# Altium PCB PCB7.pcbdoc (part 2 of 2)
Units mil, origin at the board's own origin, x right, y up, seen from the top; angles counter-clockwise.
Board outline 4082.91 x 5474.41 mil, 4 copper layers (Top Layer, Inner1, Inner2, Bottom Layer); 133 components, 162 nets, 570 pads, 328 vias.
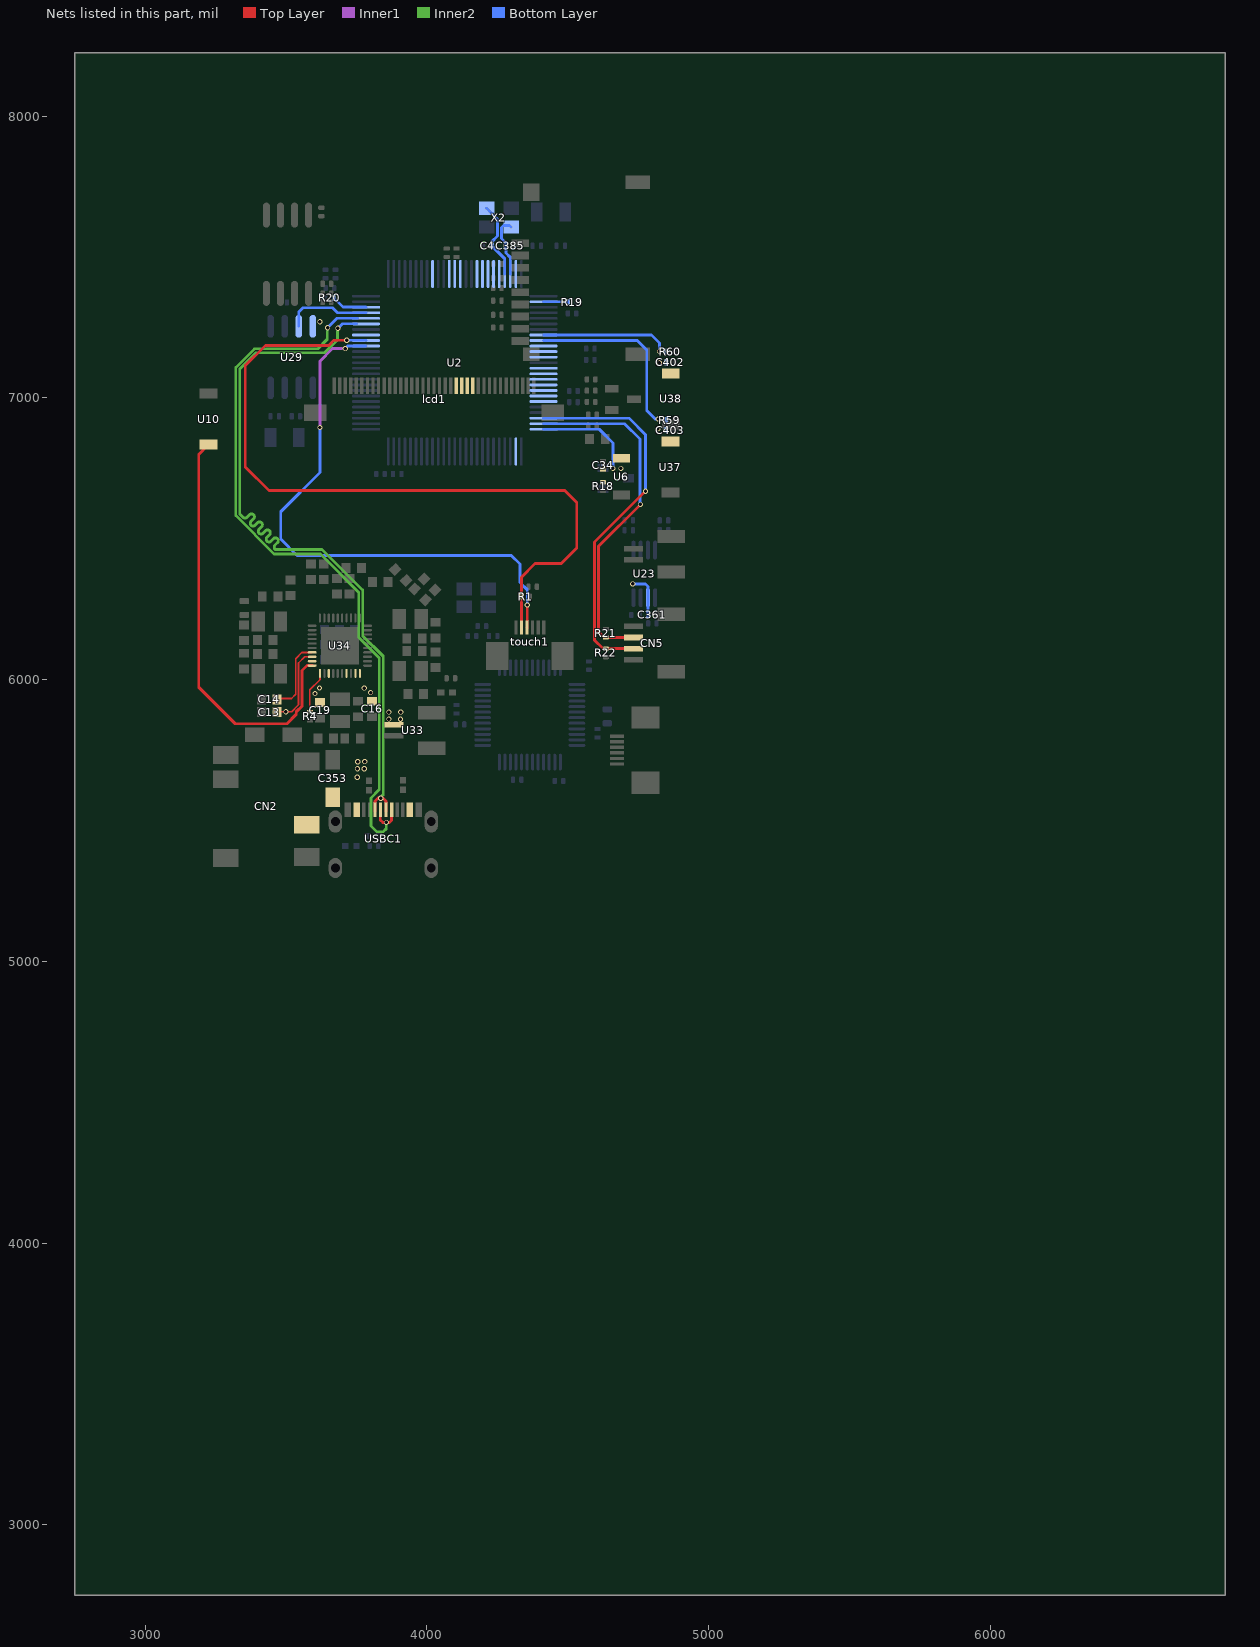
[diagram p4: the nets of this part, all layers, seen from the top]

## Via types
v1: diameter 18.5, hole 12, Top Layer to Bottom Layer, 319 vias
v2: diameter 19.7, hole 7.9, Top Layer to Bottom Layer, 9 vias

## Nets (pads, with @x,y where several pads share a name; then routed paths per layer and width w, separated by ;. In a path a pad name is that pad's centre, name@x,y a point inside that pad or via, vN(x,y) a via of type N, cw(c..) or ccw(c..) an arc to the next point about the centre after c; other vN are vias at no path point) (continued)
PB15: touch1.3 U2.41 | length 1995.7
  Top Layer w10: touch1.3@4355.16,6185.1 4355.72,6185.66 v1(4355.72,6264.41)
  Inner1 w10: v1(3620,6894.41) 3620,7129.41 3665,7174.41 v1(3710,7174.41)
  Bottom Layer w10: v1(3620,6894.41) 3620,6734.21 3481,6595.21 3481,6498.61 3539.2,6440.41 4299,6440.41 4330,6409.41 4330,6344.41 4355.72,6318.69 v1(4355.72,6264.41) ; v1(3710,7174.41) 3719.02,7183.43 U2.41@3783.82,7183.43
PC8: U2.59
PC11: U2.62
PC12: U2.63
PC13: U2.64
PD0: U2.89
PD1: U2.90
PD2: U2.91
PD3: U2.92
PD4: U2.93
PD5: U2.94
PD6: U2.95
PD9: U2.67
PD10: U2.68
PD11: U2.69
PD12: U2.70
PE0: C4.1 U2.72 X2.3 | length 276.9
  Bottom Layer w10: X2.3@4211.69,7672.87 4230,7654.56 4230,7654.37 4250.25,7634.12 4250.25,7573.8 4230,7553.55 C4.1@4230,7539.41 4275.94,7493.46 U2.72@4275.94,7439.33
PE1: C385.1 U2.73 X2.1 | length 217.4
  Bottom Layer w10: U2.73@4295.63,7439.33 4295.63,7498.78 4280,7514.41 C385.1@4280,7539.41 4280,7549.41 4264.25,7565.16 4264.25,7604.41 4271.32,7611.48 4292.77,7611.48 X2.1@4298.31,7605.94
PE2: C402.2 R60.1 U2.83 U38.2 | length 453
  Bottom Layer w10: U2.83@4413.74,7222.8 4796.61,7222.8 4825,7194.41 v1(4825,7164.41)
  other v1: 4825,7124.41
PE3: C403.2 R59.1 U2.84 U37.2 | length 647.6
  Bottom Layer w10: U2.84@4413.74,7203.11 4746.3,7203.11 4780,7169.41 4780,6954.41 4810,6924.41 v1(4820,6924.41)
  other v1: 4820,6889.41
PE4: U2.85
PE5: U2.86
PE6: U2.87
PE8: R1.1 touch1.2 U2.42 | length 2634.5
  Top Layer w10: v1(3715,7204.41) 3670,7204.41 3651.6,7186.01 3426.6,7186.01 3355,7114.41 3355,6754.41 3439,6670.41 4489.2,6670.41 4531.82,6627.79 4531.82,6467.36 4476.4,6411.94 4383.9,6411.94 4335,6363.05 R1.1@4335,6294.41 4335.47,6293.94 touch1.2@4335.47,6185.1
  Bottom Layer w10: v1(3715,7204.41) 3782.52,7204.41 U2.42@3783.82,7203.11
PE9: U2.43
PE11: U2.45 USBC1.A7 USBC1.B7 | length 2645.9
  Top Layer w10: USBC1.B7@3815.47,5532.69 3815.47,5567.95 3826.49,5578.97 v1(3835.61,5578.97) 3843.98,5578.97 3855,5567.95 3855,5532.85 USBC1.A7@3854.84,5532.69
  Inner2 w10: v1@3684.09,7246 3681.98,7243.89 3681.98,7205.37 3636.28,7159.67 3393.32,7159.67 3335.59,7101.94 3335.59,6587.76 3347.48,6575.87 ccw(c3354.56,6582.94) 3361.63,6575.87 3370.43,6584.68 cw(c3377.5,6577.61) 3384.57,6570.54 3375.77,6561.73 ccw(c3382.84,6554.66) 3389.91,6547.59 3398.72,6556.39 cw(c3405.79,6549.32) 3412.86,6542.25 3404.05,6533.45 ccw(c3411.12,6526.37) 3418.2,6519.3 3427,6528.11 cw(c3434.07,6521.04) 3441.14,6513.97 3432.34,6505.16 ccw(c3439.41,6498.09) 3446.48,6491.02 3455.29,6499.83 cw(c3462.36,6492.75) 3469.43,6485.68 3460.62,6476.88 ccw(c3467.69,6469.81) 3460.62,6462.74 3461.75,6461.61 3627.72,6461.61 3771.79,6317.55 3771.79,6155.38 3844.75,6082.42 3844.75,5590.89 v1@3835.93,5582.07
  Bottom Layer w10: v1(3683.88,7246.59) 3699.95,7262.66 U2.45@3750.56,7262.66
PE12: U2.46 USBC1.A6 USBC1.B6 | length 2645.9
  Top Layer w10: USBC1.A6@3834.35,5522.71 3834.35,5501.33 3843.37,5492.3 3867.53,5492.3 3874.66,5499.43 3874.66,5518.83 USBC1.B6@3874.97,5519.15
  Inner2 w10: 3621.57,6445.47 3757.79,6309.26 3757.67,6149.69 3830.75,6076.59 3830.75,5609.16 3801.47,5579.88 3801.47,5480.45 3822.49,5459.42 3844.42,5459.42 3855.41,5470.42 3855.41,5487.44 v1@3854.57,5488.29 ; 3621.57,6446.01 3457.55,6446.01 3321.59,6581.97 3321.59,7107.74 3387.52,7173.67 3612.34,7173.67 3646.32,7207.64 v1@3646.32,7248.37
  Bottom Layer w10: v1(3647.45,7248.41) 3681.27,7282.23 U2.46@3752.89,7282.23
  other v1: 3856.12,5492.93
PE13: U2.47 U29.7 | length 303.3
  Bottom Layer w10: U29.7@3545,7253.56 3545,7304.41 3560,7319.41 3665,7319.41 3682.87,7301.54 U2.47@3783.82,7301.54
PF1: U2.2
PF5: U2.71
PWROK: U34.29
PWRON: U10.2 U34.30 | length 1497.1
  Top Layer w10: U10.2@3225,6833.86 3190,6798.86 3190,5972.78 3319.7,5843.08 3502.72,5843.08 3536.21,5876.57 3536.21,5885.5 3556.03,5905.32 3556.03,6031.51 3574.57,6050.04 3591.75,6050.04 U34.30@3592.56,6049.23
RIGHT: C353.2 CN2.4
RST: C34.2 R18.1 U2.100 U6.1 | length 356.4
  Bottom Layer w10: U2.100@4413.74,6888.15 4611.26,6888.15 4660,6839.41 v1(4660,6749.41)
  other v1: 4688.19,6749.41
RTC: U2.74
SCK: U34.40
SDA: U34.39
SWCLK: CN5.2 R22.1 U2.98 | length 1335.9
  Top Layer w10: CN5.2@4728.07,6109.72 4624.69,6109.72 4595,6139.41 4595,6487.78 v1(4775.77,6668.55)
  Bottom Layer w10: U2.98@4413.74,6927.52 4716.89,6927.52 4775.77,6868.64 v1(4775.77,6668.55)
SWDIO: CN5.3 R21.1 U2.99 | length 1237.7
  Top Layer w10: CN5.3@4728.07,6149.09 4630.32,6149.09 4609,6170.41 4609,6473.14 v1(4757.38,6621.53)
  Bottom Layer w10: U2.99@4413.74,6907.83 4701.57,6907.83 4755.52,6853.89 4755.52,6623.39 v1(4757.38,6621.53)
TS: R4.1 U34.31 | length 152.4
  Top Layer w6: R4.1@3585,5884.41 3584.25,5885.16 3584.25,5963.66 3620.09,5999.5 U34.31@3620.09,6021.7
VBACKUP: C14.1 U34.27 | length 264.3
  Top Layer w6: C14.1@3467.56,5929.41 3470.53,5932.38 3519.28,5932.38 3534.03,5947.14 3534.03,6073.87 3556.34,6096.17 U34.27@3588.54,6096.17
VBAT: C19.2 C361.2 U23.6 U33.2 U34.33 | length 165.4
  Bottom Layer w10: v1(4730,6339.41) 4775,6339.41 4784.1,6330.31 U23.6@4784.1,6290.52 C361.2@4784.1,6222.81
  other v1: 3865,5859.41 3906.13,5858.78 3865,5884.41 3906.92,5884.41 3602.5,5950 3618.42,5970.05
VBUS: C16.1 U34.37 USBC1.A4 USBC1.A9 USBC1.B4 USBC1.B9
  other v1: 3752.62,5652.99 3753.23,5683.05 3777.42,5683.63 3754.07,5708.24 3778.99,5708.81 3800.09,5953.59 3777.54,5969.48
VCAP: R19.2 U2.77 | length 87.2
  Bottom Layer w10: U2.77@4413.74,7340.91 4498.79,7340.91 R19.2@4500.29,7339.41
VCAP_1: R20.2 U2.48 | length 127.6
  Bottom Layer w10: R20.2@3670,7354.41 3701.87,7322.54 3782.5,7322.54 U2.48@3783.82,7321.22
VRTC: C13.1 U29.8 U34.28 | length 293.5
  Top Layer w6: C13.1@3467.56,5884.41 3468.99,5885.84 v1(3499.23,5885.84) 3519.58,5885.84 3544.03,5910.29 3544.03,6058.87 3566.14,6080.98 3591.93,6080.98 U34.28@3592.42,6080.49
  other v1: 3620,7269.41
VSYS: 
XL/X-: lcd1.14
XR/X+: lcd1.12
YD/Y+: lcd1.13
YU/Y-: lcd1.15
pads on no net: C5.1 C15.1 C21.2 C394.1 C396.1 C397.1 CARD2.9 CN2.6 CN2.7 lcd1.21 R50.1 U2.82 U12.9 U12.10 U12.11 U12.12 U12.15 U12.25 U12.27 U12.36 U12.48 U34.6 U34.7 U34.17 U34.23 U34.24 U34.34 U34.36 USBC1.A8 USBC1.B8
copper on no net: | length 72.7
  Top Layer w8: v1(3659.8,5977.85) 3667.34,5985.39 3667.34,6021.7
  Top Layer w10: v1(3641.14,5960.9) 3658.09,5977.85 v1(3659.8,5977.85)
  other v1: 3752.28,5949.23 4070,6030.04 4070,6054.41 3896.85,6113.05 3484.19,6127.21 3848.95,6133.42 3876.64,6132.57 3897.33,6145.66 3505.33,6150.06 3634.56,6298.25 3634.32,6325

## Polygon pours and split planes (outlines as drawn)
GND on Inner2 (solid, remove dead copper): 3000,5079.41 5070,5079.41 5070,7974.41 3000,7974.41
DCDC1 on Top Layer (solid, remove dead copper, pour order 4): 3425.63,6240.47 3330.63,6240.47 3330.63,6170.47 3425.63,6170.47
DCDC2 on Top Layer (solid, remove dead copper, pour order 6): 3430.63,6058.52 3329.51,6058.52 3329.51,5980.47 3430.63,5980.47
GND on Top Layer (solid, remove dead copper, pour order 8): 3425.63,6165.47 3329.87,6165.47 3329.87,6072.11 3425.63,6072.11
DCDC1 on Inner1 (solid, remove dead copper): 3115,5239.41 4990,5239.41 4990,7864.41 3115,7864.41
DCDC5/VSYS on Top Layer (solid, remove dead copper, pour order 24): 3730.63,5880.47 3650.63,5880.47 3650.63,5770.47 3730.63,5770.47
GND on Bottom Layer (solid, remove dead copper, pour order 150): 3145,5254.41 4970,5254.41 4970,7849.41 3145,7849.41
DCDC4 on Top Layer (solid, remove dead copper, pour order 44): 4050.63,6250.47 3955.63,6250.47 3955.63,6180.47 4050.63,6180.47
DCDC3 on Top Layer (solid, remove dead copper, pour order 46): 4050.63,6065.47 3955.63,6065.47 3955.63,5990.47 4050.63,5990.47
GND on Top Layer (solid, remove dead copper, pour order 48): 4050.63,6169.4 3955.63,6169.4 3955.63,6080.47 4050.63,6080.47
CHGLED on Top Layer (solid, remove dead copper, pour order 62): 3806.73,6053.9 3773.24,6053.9 3773.24,5996.15 3806.73,5996.15
GND on Top Layer (solid, remove dead copper, pour order 66): 3825.66,5884.76 3737.17,5884.76 3737.17,5770.52 3825.66,5770.52
GND on Top Layer (solid, remove dead copper, pour order 68): 3744.28,6415.15 3661.87,6415.15 3661.87,6340.32 3744.28,6340.32
DCDC1 on Top Layer (solid, remove dead copper, pour order 78): 4350,6280.37 4375,6280.37 4375,6344.41 4350,6344.41
DCDC1 on Top Layer (solid, remove dead copper, pour order 96): 4622,6174.41 4760,6174.41 4760,6200.43 4622,6200.43
DCDC1 on Top Layer (solid, remove dead copper, pour order 112): 3516.42,7325.92 3627.14,7325.92 3627.14,7415.3 3516.42,7415.3
GND on Top Layer (solid, remove dead copper, pour order 120): 3070,5144.41 5020,5144.41 5020,7929.41 3070,7929.41
DC1SW on Bottom Layer (solid, remove dead copper, pour order 122): 3609.96,6201.48 3575.59,6201.13 3572.06,6201.01 3459.83,6314.23 3414.46,6314.23 3398.19,6330.5 3398.19,6355.49 3410.88,6368.18 3493.53,6368.18 3610.68,6251.03
no net on Top Layer (solid, remove dead copper): 3608.58,6165.47 3430.63,6165.47 3430.63,6070.47 3475.63,6070.47 3490.63,6085.47 3490.63,6114.32 3516.78,6140.47 3608.58,6140.47
VBUS on Inner2 (solid, remove dead copper): 3736.54,5957.69 3736.54,5645.6 3751.13,5631.01 3774.64,5630.39 3818.72,5678.21 3816.25,5966.6 3802.84,5980.01 3758.86,5980.01
no net on Inner1 (solid, remove dead copper): 3497.46,6165.87 3497.34,6165.87 3496.89,6165.42 3497.01,6165.42
CPUS_LDO on Bottom Layer (solid, remove dead copper, pour order 124): 3789.27,6196.14 3789.27,6241.76 3960.51,6413 3963.89,6413 3990.03,6386.86 3990.03,6380.37 3803.3,6193.63 3789.19,6193.63 3789.19,6196.06
VRTC on Inner1 (solid, remove dead copper): 3484.48,5870.71 3510.96,5870.71 3516.03,5875.77 3516.03,5904.98 3364.38,6056.62 3364.38,7127.94 3471.85,7235.41 3613.87,7235.41 3642.69,7264.23 3642.69,7297.33 3635.78,7304.24 3461.99,7304.24 3317.4,7159.66 3317.4,6037.78
$2N7324 on Top Layer (solid, remove dead copper, pour order 2): 3608.71,6170.47 3608.71,6180.47 3562.2,6180.47 3510.63,6232.04 3510.63,6240.47 3445.63,6240.47 3445.63,6170.47
VBAT on Bottom Layer (solid, remove dead copper, pour order 126): 3920,5899.41 3920,5839.41 3655,5839.41 3575,5919.41 3575,5989.41 3630,5989.41 3630,5954.41 3685,5899.41
VBAT on Inner1 (solid, remove dead copper): 3849.8,5897.43 3849.8,5850.88 4044.78,5655.9 4621.08,5655.9 4837.05,5871.87 4837.05,6287.54 4775.43,6349.16 4721.72,6349.16 4714.81,6342.24 4714.81,6327.89 4723.85,6318.85 4778.09,6318.85 4821.16,6275.77 4821.16,5889.16 4628.98,5696.97 4036.98,5696.97 3918.56,5815.39 3918.56,5897.58 3849.95,5897.58
CHGLED on Bottom Layer (solid, remove dead copper, pour order 128): 3775,6044.41 3775,5999.41 3855,5919.41 4065,5919.41 4065,5942.63 4063.22,5944.41 3875,5944.41 3805,6014.41 3805,6044.41
ALDO1 on Inner1 (solid, remove dead copper): 3506.04,6425.89 3506.04,6378.03 3509.94,6374.13 3542.56,6374.13 3559.57,6357.12 3845.88,6357.12 4105.25,6097.74 4105.25,5817.15 4133.37,5789.04 4439.32,5789.04 4494.94,5844.65 4494.94,5981.06 4462.23,5981.06 4447.07,5965.9 4447.07,5905.28 4413.57,5871.77 4239.67,5871.77 4191.81,5919.64 4191.81,6075.18 3841.15,6425.85 3506.06,6425.85
$3N6131 on Bottom Layer (solid, remove dead copper, pour order 130): 3630,5429.41 3721.14,5429.41 3721.14,5390.62 3630,5390.62
no net on Inner1 (solid, remove dead copper): 3805.15,6123.95 3823.76,6151.6 3888.06,6166.44 3923.74,6153.73 3920.26,6028.89 3823.21,5884.7 3572.7,5884.7 3419.39,6038.01 3419.39,6212.88 3561.32,6354.8 3664.88,6354.8 3664.88,6270.49 3590.6,6196.2 3590.6,6056.31 3627.2,6019.71 3734.56,6019.71 3782.54,6067.7
$3N6131 on Bottom Layer (solid, remove dead copper, pour order 132): 3722.86,5419.62 3722.65,5419.41 3722.86,5419.41
$2N7333 on Top Layer (solid, remove dead copper, pour order 10): 3544.22,6120.37 3513.37,6089.52 3513.37,5983.2 3510.63,5980.47 3448.3,5980.47 3448.3,6060.47 3480.63,6060.47 3494.62,6074.46 3494.62,6114.16 3515.93,6135.47 3608.71,6135.47 3608.71,6120.37
ALDO3 on Inner1 (solid, remove dead copper): 3670.56,6263.72 3678.36,6255.92 3693.96,6255.92 3699.99,6261.95 3699.99,6277.91 3712.75,6290.67 3811.67,6290.67 3984.56,6117.77 3984.56,5827.01 4093.85,5717.73 4372.24,5717.73 4383.41,5728.9 4383.41,5756.82 4367.46,5772.77 4130.54,5772.77 4022.85,5880.46 4022.85,6161.24 3848.16,6335.94 3702.18,6335.94 3670.56,6304.32
$2N7384 on Top Layer (solid, remove dead copper, pour order 12): 3690.63,6040.47 3675.63,6040.47 3675.63,5975.39 3655.63,5955.39 3655.63,5905.47 3725.63,5905.47 3725.63,5955.47 3690.63,5990.47
$3N5130 on Bottom Layer (solid, remove dead copper, pour order 134): 4819.01,6260.7 4813.96,6255.65 4804.97,6255.65 4799.91,6260.7 4799.91,6329.54 4782.49,6346.96 4756.64,6346.96 4746.24,6357.36 4746.24,6389.95 4753.83,6397.54 4791.76,6397.54 4818.45,6370.84 4818.45,6261.27
VRTC on Bottom Layer (solid, remove dead copper, pour order 136): 3630,7289.41 3585,7289.41 3585,7251.08 3629.88,7251.08 3629.88,7289.29
no net on Top Layer (solid, remove dead copper, pour order 14): 3692.84,6040.47 3706.33,6040.47 3706.33,5999.77 3745.63,5960.47 3760.63,5960.47 3775.63,5945.47 3775.63,5905.47 3735.43,5905.47 3735.43,5950.67 3692.84,5993.26
VBUS on Top Layer (solid, remove dead copper, pour order 16): 3708.62,6040.47 3720.63,6040.47 3720.63,6009.81 3738.94,5991.49 3784.61,5991.49 3825.63,5950.47 3825.63,5905.47 3785.71,5905.47 3785.71,5940.47 3760.71,5965.47 3745.63,5965.47 3708.62,6002.48
$3N5134 on Bottom Layer (solid, remove dead copper, pour order 138): 4695,6324.41 4740,6324.41 4740,6254.41 4695,6254.41
PE2 on Bottom Layer (solid, remove dead copper, pour order 140): 4860.64,7181.24 4817.61,7181.24 4814.26,7177.9 4814.26,7114.39 4821.19,7107.46 4860.51,7107.46 4860.55,7107.43 4860.64,7107.52
ALDO3 on Top Layer (solid, remove dead copper, pour order 18): 3690.63,6200.47 3675.63,6200.47 3675.63,6265.47 3660.63,6280.47 3660.63,6320.47 3700.94,6320.47 3700.94,6275.77 3690.63,6265.47
ALDO4 on Top Layer (solid, remove dead copper, pour order 20): 3692.37,6262.2 3703.24,6273.08 3703.24,6320.47 3745.63,6320.47 3745.63,6285.47 3705.63,6245.47 3705.63,6200.39 3692.37,6200.39
PE3 on Bottom Layer (solid, remove dead copper, pour order 142): 4859.41,6936.15 4810.38,6936.15 4810,6935.77 4810,6872.31 4808.86,6871.17 4858.27,6871.17 4859.41,6872.31
VBAT on Top Layer (solid, remove dead copper, pour order 22): 3658.39,6038.29 3645.63,6038.29 3645.63,6010.47 3590.63,5955.47 3590.63,5900.47 3645.63,5900.47 3645.63,5935.47 3630.63,5950.47 3630.63,5965.47 3658.39,5993.23
no net on Bottom Layer (solid, remove dead copper, pour order 144): 3935,6019.41 3967.94,6066.47 3970,6064.41 4080,6064.41 4080,6019.41
no net on Bottom Layer (solid, remove dead copper, pour order 146): 3920,6114.41 3967.94,6066.47 4005,6119.41 3920,6139.41
no net on Top Layer (solid, remove dead copper, pour order 26): 3674.01,6201.88 3674.01,6264.48 3655.63,6282.86 3655.63,6370.47 3610.63,6370.47 3610.63,6303.53 3659.04,6255.13 3659.04,6201.88
no net on Bottom Layer (solid, remove dead copper, pour order 148): 3920,6159.41 3920,6139.41 3835,6159.41
ALDO1 on Top Layer (solid, remove dead copper, pour order 28): 3655.63,6200.47 3655.63,6255.47 3605.63,6305.47 3605.63,6370.47 3570.23,6370.47 3570.23,6325.87 3645.63,6250.47 3645.63,6200.47
ALDO2 on Top Layer (solid, remove dead copper, pour order 30): 3642.51,6248.59 3560.63,6330.47 3560.63,6350.47 3540.63,6370.47 3495.63,6370.47 3495.63,6335.47 3530.63,6335.47 3630.63,6235.47 3630.63,6200.47 3642.51,6200.47
DC1SW on Top Layer (solid, remove dead copper, pour order 32): 3625.63,6200.47 3625.63,6235.95 3606.11,6255.47 3605.63,6255.47 3580.63,6280.47 3541.95,6280.47 3541.95,6231.65 3573.13,6200.47
GND on Top Layer (solid, remove dead copper, pour order 34): 3535.63,6275.47 3450.63,6275.47 3450.63,6315.16 3535.32,6315.16 3535.63,6315.47
DC1SW on Top Layer (solid, remove dead copper, pour order 36): 3435.63,6275.47 3435.63,6315.47 3445.63,6325.47 3485.63,6325.47 3485.63,6369.37 3409.53,6369.37 3395.63,6355.47 3395.63,6275.47
BLDO2 on Top Layer (solid, remove dead copper, pour order 38): 3710.63,6200.47 3710.63,6246.45 3750.63,6286.45 3750.63,6415.47 3785.63,6415.47 3785.63,6302.52 3720.63,6237.52 3720.63,6200.47
BLDOIN on Top Layer (solid, remove dead copper, pour order 40): 3788.58,6365.47 3824.44,6365.47 3824.44,6304.27 3805.63,6285.47 3785.68,6285.47 3735.63,6235.42 3735.63,6200.47 3724.77,6200.47 3724.77,6239.39 3788.58,6303.2
$2N7343 on Top Layer (solid, remove dead copper, pour order 42): 3813.81,6166.06 3843.71,6195.96 3843.71,6231.62 3862.56,6250.47 3925.63,6250.47 3925.63,6180.47 3894.31,6180.47 3866.35,6152.51 3771.98,6152.51 3771.98,6166.06
no net on Top Layer (solid, remove dead copper, pour order 50): 3945.63,6080.47 3905.63,6080.47 3865.63,6120.47 3771.07,6120.47 3771.07,6148.96 3869.13,6148.96 3885.63,6165.47 3945.63,6165.47
$2N7338 on Top Layer (solid, remove dead copper, pour order 52): 3770.63,6118.22 3857.88,6118.22 3910.63,6065.47 3925.31,6065.47 3925.31,5995.47 3867.12,5995.47 3867.12,6073.97 3835.63,6105.47 3770.63,6105.47
$2N7386 on Top Layer (solid, remove dead copper, pour order 54): 3770.35,6072.48 3835.98,6072.48 3848.77,6059.7 3848.77,5993.81 3872.14,5970.43 3950.35,5970.43 3950.35,5926.99 3929.34,5927.27 3908.42,5927.37 3881.96,5927.37 3816.59,5992.73 3816.59,6044.97 3802.41,6059.14 3770.35,6059.14
BLDO1 on Top Layer (solid, remove dead copper, pour order 56): 3737.98,6201.7 3737.98,6235.77 3786.67,6284.46 3806.45,6284.46 3842.16,6320.16 3874.79,6320.16 3883.9,6329.28 3883.9,6334.74 3925.71,6376.55 3927.58,6376.55 3950.82,6353.31 3950.82,6351.6 3895.12,6295.9 3850.01,6295.9 3824.56,6270.44 3789.36,6270.44 3752.91,6233.99 3752.91,6201.7
DC4SW on Top Layer (solid, remove dead copper, pour order 58): 3932.59,6274.09 3981.91,6323.41 3957.82,6347.5 3957.71,6347.5 3903.6,6293.4 3851.26,6293.4 3825.97,6268.11 3790.95,6268.11 3755.58,6232.74 3755.58,6201.81 3755.41,6201.64 3767.2,6201.64 3768.05,6202.5 3768.05,6225.56 3796.76,6254.27 3836.91,6254.27 3856.73,6274.09
CPUS_LDO on Top Layer (solid, remove dead copper, pour order 60): 4017.61,6357.75 3988.64,6328.79 3988.64,6328.45 3931.92,6385.17 3961.65,6414.9 3961.91,6414.9 4017.61,6359.2
CPUS_LDO on Top Layer (solid, remove dead copper, pour order 64): 3771.93,6186.1 3803.59,6186.1 3803.71,6185.99 3819.54,6201.82 3819.54,6238.16 3809.17,6248.52 3795.96,6248.52 3771.93,6224.49
$1N13562 on Top Layer (solid, remove dead copper, pour order 70): 4615,6874.41 4675,6874.41 4710,6909.41 4710,7009.41 4760,7009.41 4760,6874.41 4720,6834.41 4615,6834.41
IM0 on Top Layer (solid, remove dead copper, pour order 72): 4560.26,6954.41 4585,6954.41 4585,6884.31 4560.26,6884.31
$1N13566 on Top Layer (solid, remove dead copper, pour order 74): 4590,7079.41 4590,6973.64 4603.55,6973.64 4642.25,7012.34 4681.04,7012.34 4681.04,7049.41 4642.3,7049.41 4612.3,7079.41
LED_K on Top Layer (solid, remove dead copper, pour order 76): 4035,6984.41 4070,6949.41 4105,6949.41 4145,6909.41 4145,6864.41 4180,6829.41 4595,6829.41 4595,6872.91 4210,6872.91 4185,6897.91 4185,6912.8 4113.39,6984.41
VBAT on Top Layer (solid, remove dead copper, pour order 80): 3850,5899.2 3850,5829.41 3920,5829.41 3920,5899.2
LEFT on Top Layer (solid, remove dead copper, pour order 82): 3350,5834.41 3350,5694.41 3340,5684.41 3245,5684.41 3235,5674.41 3235,5614.41 3240,5609.41 3335,5609.41 3425,5699.41 3425,5834.41
RIGHT on Top Layer (solid, remove dead copper, pour order 84): 3693.07,5619.59 3600.19,5619.59 3525,5544.41 3525,5449.41 3622.77,5449.41 3622.77,5527.18 3640,5544.41 3693.07,5544.41
DCDC1 on Top Layer (solid, remove dead copper, pour order 86): 4256.26,7378.15 4282.49,7378.15 4290,7385.66 4290,7394.41 4300,7404.41 4420,7404.41 4420,7438.63 4256.26,7438.63
RST on Top Layer (solid, remove dead copper, pour order 88): 4611.57,6690.25 4611.57,6754.84 4644.38,6754.84 4659.79,6770.25 4659.79,6805.25 4719.79,6805.25 4719.79,6760.53 4649.5,6690.25
$2N1132 on Top Layer (solid, remove dead copper, pour order 90): 4080,5974.92 4091.95,5986.87 4091.95,6016.97 4108.26,6016.97 4108.26,5942.53 4080,5942.53
CHGLED on Top Layer (solid, remove dead copper, pour order 92): 4067.2,5967.38 4067.2,5915.49 4018.58,5915.49 4018.58,5967.38
no net on Top Layer (solid, remove dead copper, pour order 94): 4060,6064.41 4080,6064.41 4080,5991.44 4060,5991.44
VRTC on Top Layer (solid, remove dead copper, pour order 98): 3515.32,5904.41 3450,5904.41 3450,5867.06 3515.32,5867.06
$3N6131 on Top Layer (solid, remove dead copper, pour order 100): 3525,5429.41 3720,5429.41 3720,5389.1 3659.69,5389.1 3625,5354.41 3625,5338.52 3525,5338.52
VBUS on Top Layer (solid, remove dead copper, pour order 102): 3738.46,5563.77 3738.46,5492.96 3787.77,5443.65 3896.65,5443.65 3951.72,5498.72 3951.72,5563.63 3951.44,5563.91 3927.56,5563.91 3927.28,5563.63 3927.28,5509.68 3897.89,5480.29 3794.27,5480.29 3762.35,5512.21 3762.35,5563.06 3762.44,5563.16 3739.21,5563.16 3738.59,5563.78 3738.57,5563.77
VBUS on Top Layer (solid, remove dead copper, pour order 104): 3738.3,5511.49 3761.62,5511.49 3761.91,5511.77 3761.91,5651.65 3798.99,5688.74 3798.99,5722.36 3793.06,5728.29 3745.5,5728.29 3737.36,5720.15 3737.36,5512.44
$3N5130 on Top Layer (solid, remove dead copper, pour order 106): 4698.01,6410.19 4736.65,6410.19 4745.64,6401.2 4745.64,6346.63 4773.25,6346.63 4785.68,6359.05 4785.68,6434.49 4781.18,6438.99 4698.01,6438.99
$3N5134 on Top Layer (solid, remove dead copper, pour order 108): 4770,6449.41 4770,6499.41 4652.94,6499.41 4622,6468.47 4622,6277.41 4645,6254.41 4724.93,6254.41 4724.93,6319.48 4715,6329.41 4670,6329.41 4660,6339.41 4660,6434.41 4675,6449.41
ALDO1 on Top Layer (solid, remove dead copper, pour order 110): 3605.95,6339.24 3605.95,6382.65 3599.73,6388.87 3570.26,6388.87 3566.08,6393.05 3566.08,6426.69 3505.58,6426.69 3505.58,6374.54 3541.98,6374.54 3569.63,6346.88 3569.63,6339.32 3569.71,6339.24
DCDC1 on Top Layer (solid, remove dead copper, pour order 114): 3425.63,6240.23 3425.63,6169.41 3208.85,6169.41 3208.85,6239.41 3424.81,6239.41
PE3 on Top Layer (solid, remove dead copper, pour order 116): 4895.94,6863.65 4895.94,6825.64 4894.93,6824.63 4818.92,6824.63 4806,6837.55 4806,6936.36 4806.25,6936.61 4828.29,6936.61 4830.07,6934.84 4830.07,6868.71 4890.62,6868.71 4892.14,6867.19 4892.39,6867.19
PE2 on Top Layer (solid, remove dead copper, pour order 118): 4898.89,7104.88 4898.89,7068.39 4896.61,7066.11 4831.24,7066.11 4813,7084.36 4813,7170.84 4817.77,7175.61 4833.31,7175.61 4842.26,7166.66 4842.26,7114.63 4847.83,7109.06 4894.71,7109.06

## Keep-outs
Board Outline Layer:
  lines w3.94: 3162.23,5342.09 3162.23,7585.68 3319.71,7585.68 3319.71,7664.42 3162.23,7664.42 3162.23,7743.66 cw(c3240.47,7743.66) 3240.47,7821.9 4854.64,7821.9 cw(c4854.64,7743.66) 4932.88,7743.66 4932.88,5500.07 4775.4,5500.07 4775.4,5421.33 4932.88,5421.33 4932.88,5342.09 cw(c4854.64,5342.09) 4854.64,5263.85 3240.47,5263.85 cw(c3240.47,5342.09) 3162.23,5342.09
Multi-Layer:
  region: 4536.56,5581.38 4064.11,5581.38 4064.11,5482.95 4536.56,5482.95
  region: 4476.46,6586.51 3570.95,6586.51 3570.95,6488.08 4476.46,6488.08

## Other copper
Top Layer:
  region net MP3_LEFT: 3565.59,5767.28 3547.72,5771.01 ccw(c3525.64,5748.93) 3534.4,5778.9 3555.99,5778.9 ccw(c3621.96,5823.66)
  region net $1N8688: 4377.84,7552.99 4377.84,7542.99 ccw(c4377.84,7524.24) 4362.84,7535.49 4362.84,7560.49 ccw(c4377.84,7571.74)
  region net CS: 4284.84,7499.68 4284.84,7509.68 ccw(c4284.84,7528.43) 4299.84,7517.18 4299.84,7492.18 ccw(c4284.84,7480.93)
  region net MOSI: 4284.84,7456.38 4284.84,7466.38 ccw(c4284.84,7485.13) 4299.84,7473.88 4299.84,7448.88 ccw(c4284.84,7437.63)
  region net CLK: 4295.35,7369.76 4295.35,7379.76 ccw(c4291.34,7387.26) 4299.84,7387.26 4299.84,7362.26 ccw(c4291.34,7362.26)
  region net MISO: 4284.84,7289.41 4284.84,7299.41 ccw(c4284.84,7345.32) 4299.84,7301.93 4299.84,7281.91 ccw(c4284.84,7270.66)
  region net $1N8688: 4284.84,7239.84 4284.84,7249.84 ccw(c4284.84,7268.59) 4299.84,7257.34 4299.84,7232.34 ccw(c4284.84,7221.09)
  region net $1N8688: 4377.84,7254.41 4377.84,7244.41 ccw(c4377.84,7225.66) 4362.84,7236.91 4362.84,7258.62 ccw(c4377.84,7283.24)
  region net GBUF: 3291.3,5333.11 3281.3,5333.11 ccw(c3273.8,5317.76) 3273.8,5334.84 3298.8,5334.84 ccw(c3298.8,5317.76)
  region net ALDO3: 4713.92,5725.04 4713.92,5715.04 ccw(c4713.92,5609.14) 4698.92,5713.97 4698.92,5725.78 ccw(c4713.92,5876.76)
  region net MICN: 4634.84,5754.25 4634.84,5764.25 ccw(c4634.84,5886.69) 4649.7,5765.15 4649.7,5753.34 ccw(c4634.84,5631.81)
  region net ALDO3: 4711.03,5784.24 4711.03,5774.24 ccw(c4711.03,5712.75) 4698.92,5773.03 4698.92,5784.84 ccw(c4711.03,5905.41)
  region net PWRON: 3206.46,6808.25 3186.89,6802.82 ccw(c3164.81,6824.9) 3194.78,6816.14 3219.78,6816.14 ccw(c3228.54,6786.17)
  region net SWDIO: 4684.61,6144.09 4684.61,6154.09 ccw(c4684.61,6179.74) 4699.61,6158.93 4699.61,6139.25 ccw(c4684.61,6118.44)
  region net SWCLK: 4684.61,6104.72 4684.61,6114.72 ccw(c4684.61,6140.37) 4699.61,6119.56 4699.61,6099.88 ccw(c4684.61,6079.07)
  region net DCDC1: 4127.62,7534.41 4127.62,7524.41 ccw(c4127.62,7478.16) 4112.62,7521.91 4112.62,7536.91 ccw(c4127.62,7580.66)
  region net DCDC1: 4082.38,7524.41 4082.38,7534.41 ccw(c4082.38,7580.66) 4097.38,7536.91 4097.38,7521.91 ccw(c4082.38,7478.16)
  region net TS: 3581.25,5900.91 3587.25,5900.91 ccw(c3598.5,5900.91) 3591.75,5891.91 3577.75,5891.91 ccw(c3567.93,5900.91)
  region net DCDC1: 4630.44,6647.75 4620.44,6647.75 ccw(c4580.16,6647.75) 4617.54,6662.75 4632.04,6662.75 ccw(c4701.44,6647.75)
  region net SWDIO: 4614.73,6157.61 4624.27,6162.21 ccw(c4640.18,6183.43) 4640.18,6156.91 4624,6145.66 ccw(c4572.07,6114.94)
  region net SWDIO: 4657.25,6154.09 4657.25,6144.09 ccw(c4657.25,6091.44) 4642.25,6141.91 4642.25,6156.91 ccw(c4657.25,6195.42)
  region net DCDC1: 4612.75,6074.41 4612.75,6084.41 ccw(c4612.75,6130.66) 4627.75,6086.91 4627.75,6071.91 ccw(c4612.75,6028.16)
  region net SWCLK: 4657.25,6114.72 4657.25,6104.72 ccw(c4657.25,6063.31) 4642.25,6101.91 4642.25,6116.91 ccw(c4657.25,6167.23)
  region net SWCLK: 4612.23,6115.11 4615.55,6125.93 ccw(c4651.74,6162.11) 4627.75,6116.91 4624,6105.66 ccw(c4574.95,6056.61)
  region net DCDC1: 4240,7234.41 4230,7234.41 ccw(c4216.74,7234.41) 4227.5,7242.16 4242.5,7242.16 ccw(c4253.26,7234.41)
  region net $1N8688: 4287.5,7249.84 4283.75,7239.84 ccw(c4283.75,7160.45) 4268.75,7238.41 4272.5,7256.66 ccw(c4287.5,7269.74)
  region net MISO: 4255.23,7275.71 4251.66,7286.28 ccw(c4234.33,7301.66) 4257.5,7301.66 4268.75,7283.41 ccw(c4276.02,7254.93)
  region net MISO: 4287.5,7299.41 4287.5,7289.41 ccw(c4287.5,7238.28) 4272.5,7287.16 4272.5,7301.66 ccw(c4287.5,7350.53)
  region net DCDC1: 4212.5,7341.33 4212.5,7351.33 ccw(c4212.5,7691.78) 4227.5,7351.66 4227.5,7337.16 ccw(c4212.5,7312.26)
  region net CLK: 4255.81,7325.14 4252.2,7335.67 ccw(c4230.98,7351.58) 4257.5,7351.58 4268.75,7333.41 ccw(c4281.05,7299.9)
  region net CLK: 4279.45,7365.93 4279.27,7351.61 ccw(c4295.84,7335.04) 4272.5,7337.16 4268.75,7355.41 ccw(c3650.71,7994.67)
  region net DCDC1: 4212.5,7469.41 4212.5,7479.41 ccw(c4212.5,7530.53) 4227.5,7481.66 4227.5,7467.16 ccw(c4212.5,7418.28)
  region net MOSI: 4270,7460.27 4260,7460.27 ccw(c4249.25,7460.27) 4257.5,7467.16 4272.5,7467.16 ccw(c4280.75,7460.27)
  region net DCDC1: 4047.38,7524.41 4047.38,7534.41 ccw(c4047.38,7580.66) 4062.38,7536.91 4062.38,7521.91 ccw(c4047.38,7478.16)
  region net DCDC1: 4092.62,7534.41 4092.62,7524.41 ccw(c4092.62,7478.16) 4077.62,7521.91 4077.62,7536.91 ccw(c4092.62,7580.66)
  region net ALDO3: 3362.01,6294.52 3378.28,6296.65 ccw(c3462.13,6212.8) 3368.35,6285.37 3346.11,6289.22 ccw(c3346.11,6315.74)
  region net VRTC: 3492.31,5888.84 3492.31,5882.84 ccw(c3492.31,5871.59) 3483.31,5878.34 3483.31,5893.34 ccw(c3492.31,5900.09)
  region net VBACKUP: 3492.31,5935.38 3492.31,5929.38 ccw(c3492.31,5918.13) 3483.31,5924.88 3483.31,5939.88 ccw(c3492.31,5946.63)
  region net GND: 3454.74,6271.87 3449.64,6280.91 ccw(c3428.42,6296.82) 3454.94,6296.82 3470.65,6277.17 ccw(c3470.65,6250.66)
  region net DCDC1: 3401.38,6241.84 3411.38,6241.84 ccw(c3418.88,6271.25) 3418.88,6240.9 3393.88,6240.9 ccw(c3393.88,6271.25)
  region net DCDC2: 3406.26,5984.84 3396.26,5984.84 ccw(c3388.76,5842.17) 3388.76,5985.03 3413.76,5985.03 ccw(c3413.76,5842.17)
  region net DCDC4: 3975,6251.1 3985,6251.1 ccw(c3992.5,6393.77) 3992.5,6250.9 3967.5,6250.9 ccw(c3967.5,6393.77)
  region net DCDC3: 3981.97,5989.73 3962.1,5984 ccw(c3956.35,5989.75) 3962.52,5995.03 3997.88,5995.03 ccw(c3997.88,5968.52)
  region net TS: 3623.09,6000.89 3617.09,6000.89 3616.95,6004.05 3616.63,6006.7 3616.16,6009.89 3624.03,6009.89 3623.56,6006.7 3623.24,6004.05
  region net GND: 3772.89,6085.48 3772.89,6075.48 ccw(c3772.89,6056.73) 3757.89,6067.98 3757.89,6092.98 ccw(c3772.89,6104.23)
  region net IM0: 4187.32,6998.11 4177.32,6998.11 ccw(c4026.77,6998.11) 4176.57,7013.11 4188.38,7013.11 ccw(c4293.79,6998.11)
  region net DCDC1: 4079.05,7087.17 4089.05,7087.17 ccw(c4213.75,7087.17) 4089.96,7072.17 4078.15,7072.17 ccw(c3954.36,7087.17)
  region net LED_K: 4069.38,6998.11 4059.38,6998.11 ccw(c3934.68,6998.11) 4058.47,7013.11 4070.28,7013.11 ccw(c4194.07,6998.11)
  region net LED_K: 4049.68,6998.11 4039.68,6998.11 ccw(c3914.99,6998.11) 4038.78,7013.11 4050.59,7013.11 ccw(c4174.38,6998.11)
  region net LED_K: 4030.01,6998.11 4020.01,6998.11 ccw(c3895.31,6998.11) 4019.1,7013.11 4030.91,7013.11 ccw(c4154.7,6998.11)
  region net LED_K: 4010.32,6998.11 4000.32,6998.11 ccw(c3875.62,6998.11) 3999.41,7013.11 4011.22,7013.11 ccw(c4135.01,6998.11)
  region net LCD_RST: 3782.28,7087.17 3792.28,7087.17 ccw(c3840.22,7087.17) 3794.69,7072.17 3782.88,7072.17 ccw(c3593.95,7072.17)
  region net DCDC1: 3774.09,6998.11 3764.09,6998.11 ccw(c3639.4,6998.11) 3763.19,7013.11 3775,7013.11 ccw(c3898.79,6998.11)
  region net DCDC1: 3754.41,6998.11 3744.41,6998.11 ccw(c3619.72,6998.11) 3743.51,7013.11 3755.32,7013.11 ccw(c3879.11,6998.11)
  region net DCDC1: 3744.41,7087.17 3754.41,7087.17 ccw(c3879.11,7087.17) 3755.32,7072.17 3743.51,7072.17 ccw(c3619.72,7087.17)
  region net FLASH_CS: 3620,7696.91 3630,7696.91 ccw(c3681.13,7696.91) 3632.25,7681.91 3617.75,7681.91 ccw(c3568.87,7696.91)
  region net FLASH_CS: 3647.25,7679.41 3647.25,7669.41 ccw(c3647.25,7623.16) 3632.25,7666.91 3632.25,7681.91 ccw(c3647.25,7725.66)
  region net DCDC1: 3647.25,7649.41 3647.25,7639.41 ccw(c3647.25,7593.16) 3632.25,7636.91 3632.25,7651.91 ccw(c3647.25,7695.66)
  region net FLASH_CS: 3575,7695.28 3585,7695.28 3585.08,7693.89 3585.32,7692.52 3586.16,7689.91 3587.34,7687.5 3588.7,7685.34 3591.24,7681.99 3592.08,7680.9 3592.4,7680.28 3567.6,7680.28 3567.92,7680.9 3568.76,7681.99 3571.3,7685.34 3572.66,7687.5 3573.84,7689.91 3574.68,7692.52 3574.92,7693.89
  region net FLASH_MISO: 3525,7695.28 3535,7695.28 3535.08,7693.89 3535.32,7692.52 3536.16,7689.91 3537.34,7687.5 3538.7,7685.34 3541.24,7681.99 3542.08,7680.9 3542.4,7680.28 3517.6,7680.28 3517.92,7680.9 3518.76,7681.99 3521.3,7685.34 3522.66,7687.5 3523.84,7689.91 3524.68,7692.52 3524.92,7693.89
  region net DCDC1: 3475,7695.28 3485,7695.28 3485.08,7693.89 3485.32,7692.52 3486.16,7689.91 3487.34,7687.5 3488.7,7685.34 3491.24,7681.99 3492.08,7680.9 3492.4,7680.28 3467.6,7680.28 3467.92,7680.9 3468.76,7681.99 3471.3,7685.34 3472.66,7687.5 3473.84,7689.91 3474.68,7692.52 3474.92,7693.89
  region net FLASH_CLK: 3475.02,7417.34 3485.02,7417.3 3485.1,7415.85 3485.34,7414.6 3485.7,7413.53 3486.17,7412.61 3487.36,7411.09 3488.71,7409.8 3490.07,7408.52 3491.25,7407 3491.72,7406.07 3492.09,7405 3492.32,7403.76 3492.4,7402.3 3467.6,7402.34 3467.68,7403.79 3467.92,7405.04 3468.29,7406.11 3468.76,7407.03 3469.95,7408.55 3471.31,7409.84 3472.67,7411.12 3473.86,7412.64 3474.33,7413.56 3474.7,7414.63 3474.93,7415.88
  region net FLASH_MOSI: 3425,7417.32 3435,7417.32 3435.08,7415.93 3435.32,7414.56 3436.16,7411.95 3437.34,7409.54 3438.7,7407.38 3441.24,7404.03 3442.08,7402.94 3442.4,7402.32 3417.6,7402.32 3417.92,7402.94 3418.76,7404.03 3421.3,7407.38 3422.66,7409.54 3423.84,7411.95 3424.68,7414.56 3424.92,7415.93
  region net $1N19277: 3918.9,5582.67 3908.9,5582.67 ccw(c3885.14,5582.67) 3903.57,5597.67 3924.83,5597.67 ccw(c3940.85,5582.67)
  region net $1N19279: 3800.79,5580.77 3790.79,5580.77 ccw(c3771.97,5580.77) 3783.34,5595.77 3804.6,5595.77 ccw(c3832.26,5580.77)
  region net PE12: 3839.35,5501.33 3829.35,5501.33 ccw(c3200.8,5501.33) 3829.25,5512.1 3841.07,5512.1 ccw(c3873.96,5501.33)
  region net PE11: 3850,5567.95 3860,5567.95 ccw(c3875.02,5567.95) 3860.75,5563.28 3848.93,5563.28 ccw(c3839.22,5567.95)
  region net PE12: 3879.66,5499.43 3869.66,5499.43 ccw(c3791.3,5499.43) 3868.62,5512.1 3880.44,5512.1 ccw(c3983.04,5499.43)
  region net $1N19277: 3908.9,5578.28 3918.9,5578.28 ccw(c4043.59,5578.28) 3919.81,5563.28 3907.99,5563.28 ccw(c3784.21,5578.28)
  region net DCDC1: 4560.22,7087.56 4570.22,7091.31 ccw(c4692.07,7091.31) 4571.15,7076.31 4559.9,7072.56 ccw(c4211.98,7087.56)
  region net DCDC1: 4624.9,6905.31 4624.9,6895.31 ccw(c4624.9,6844.18) 4609.9,6893.06 4609.9,6907.56 ccw(c4624.9,6956.43)
  region net IM0: 4568.65,6888 4561.58,6895.07 ccw(c4539.76,6907.56) 4564.9,6907.56 4576.15,6889.31 ccw(c4576.15,6867.18)
  region net PE8: 4330,6316.66 4340,6316.66 ccw(c4386.25,6316.66) 4342.5,6301.66 4327.5,6301.66 ccw(c4283.75,6316.66)
  region net PE8: 4340.47,6272.16 4330.47,6272.16 ccw(c4291.11,6272.16) 4327.5,6287.16 4342.5,6287.16 ccw(c4396.9,6272.16)
  region net DCDC1: 4355,6351.66 4365,6351.66 ccw(c4411.25,6351.66) 4367.5,6336.66 4352.5,6336.66 ccw(c4308.75,6351.66)
  region net PB8: 4385,6351.66 4395,6351.66 ccw(c4441.25,6351.66) 4397.5,6336.66 4382.5,6336.66 ccw(c4338.75,6351.66)
  region net PB8: 4395,6307.16 4385,6307.16 ccw(c4338.75,6307.16) 4382.5,6322.16 4397.5,6322.16 ccw(c4441.25,6307.16)
  region: 3646.55,5973.37 3653.62,5966.3 3652.48,5965.03 3651.47,5963.58 3650.72,5962.01 3650.38,5960.38 3640.63,5970.14 3642.26,5970.48 3643.83,5971.22 3645.28,5972.23
  region: 3652.94,5965.63 3647.15,5973.97 3648.3,5975.2 3649.36,5976.54 3650.2,5978 3650.71,5979.56 3659.11,5968.62 3657.41,5968.45 3655.78,5967.79 3654.27,5966.8
  region: 3664.52,5988.22 3670.17,5982.56 3669.36,5981.4 3669.07,5980.19 3669.04,5977.33 3659.29,5987.08 3662.14,5987.12 3663.36,5987.41
  region net DB4: 4107.53,6909.81 4114.6,6916.88 4115.87,6915.75 4117.32,6914.73 4118.89,6913.99 4120.51,6913.65 4110.76,6903.89 4110.42,6905.52 4109.68,6907.09 4108.66,6908.54
  region net DB5: 3705,6740.54 3715,6740.85 3715.1,6739.14 3715.42,6737.4 3716.03,6735.76 3716.96,6734.38 3703.18,6734.06 3704.06,6735.47 3704.62,6737.11 3704.91,6738.84
  region net LCD_RD: 4052.47,7229.01 4045.4,7221.93 4044.13,7223.07 4042.68,7224.09 4041.11,7224.83 4039.49,7225.17 4049.24,7234.92 4049.58,7233.3 4050.32,7231.73 4051.34,7230.27
  region net LCD_RS: 4171.11,7192.64 4164.04,7185.57 4162.77,7186.71 4161.32,7187.72 4159.75,7188.47 4158.12,7188.81 4167.87,7198.56 4168.21,7196.94 4168.96,7195.36 4169.97,7193.91
  region net DB3: 3985,7326.13 3975,7327.97 3974.95,7329.65 3974.75,7331.35 3974.32,7332.98 3973.58,7334.45 3987.24,7332.61 3986.16,7331.29 3985.47,7329.67 3985.11,7327.9
  region net DB1: 4325.4,6971.88 4332.47,6964.81 4331.34,6963.54 4330.32,6962.09 4329.58,6960.52 4329.24,6958.89 4319.49,6968.65 4321.11,6968.99 4322.68,6969.73 4324.13,6970.75
  region net DB0: 4332.64,6939.91 4332.64,6929.91 4330.94,6929.82 4329.2,6929.51 4327.56,6928.92 4326.17,6928.01 4326.17,6941.8 4327.56,6940.9 4329.2,6940.31 4330.94,6940
  region net LCD_RST: 4067.02,7359.41 4067.02,7369.41 4068.72,7369.5 4070.46,7369.81 4072.1,7370.4 4073.49,7371.3 4073.49,7357.51 4072.1,7358.42 4070.46,7359.01 4068.72,7359.32
  region net PE8: 3702.36,7199.41 3702.36,7209.41 3704.06,7209.5 3705.8,7209.81 3707.44,7210.4 3708.83,7211.3 3708.83,7197.51 3707.44,7198.42 3705.8,7199.01 3704.06,7199.32
  region net PB8: 3667.53,7154.81 3674.6,7161.88 3675.87,7160.75 3677.32,7159.73 3678.89,7158.99 3680.51,7158.65 3670.76,7148.89 3670.42,7150.52 3669.68,7152.09 3668.66,7153.54
  region net DCDC1: 4365,6346.77 4355,6346.77 4354.91,6348.47 4354.6,6350.21 4354.01,6351.85 4353.11,6353.24 4366.89,6353.24 4365.99,6351.85 4365.4,6350.21 4365.09,6348.47
  region net PA1: 4613.45,5958.66 4613.45,5948.66 4611.75,5948.56 4610.01,5948.25 4608.37,5947.67 4606.98,5946.76 4606.98,5960.55 4608.37,5959.64 4610.01,5959.06 4611.75,5958.75
  region net PA1: 4661.25,5986.13 4651.25,5986.13 4651.16,5987.84 4650.85,5989.58 4650.26,5991.22 4649.36,5992.61 4663.14,5992.61 4662.24,5991.22 4661.65,5989.58 4661.34,5987.84
  region net PA7: 4531.9,6253.22 4523.25,6247.72 4522.04,6248.89 4520.73,6249.96 4519.3,6250.83 4517.75,6251.38 4528.95,6259.43 4528.94,6258.57 4529.08,6257.72 4529.72,6256.07 4530.71,6254.56
  region net PA7: 4334.98,5850.36 4334.98,5840.36 4333.27,5840.27 4331.53,5839.95 4329.89,5839.37 4328.5,5838.46 4328.5,5852.25 4329.89,5851.34 4331.53,5850.76 4333.27,5850.45
  region net PA6: 4545,6191.77 4535,6191.77 4534.91,6193.47 4534.6,6195.21 4534.01,6196.85 4533.11,6198.24 4546.89,6198.24 4545.99,6196.85 4545.4,6195.21 4545.09,6193.47
  region net PA6: 4302.64,5909.41 4302.64,5899.41 4300.94,5899.32 4299.2,5899.01 4297.56,5898.42 4296.17,5897.51 4296.17,5911.3 4297.56,5910.4 4299.2,5909.81 4300.94,5909.5
  region net SWCLK: 4770.37,6656.08 4763.3,6663.15 4764.44,6664.42 4765.45,6665.87 4766.2,6667.44 4766.54,6669.07 4776.29,6659.32 4774.66,6658.98 4773.09,6658.23 4771.64,6657.22
  region net DCDC1: 4613.23,6084.41 4617.27,6074.41 4615.07,6074.52 4613.13,6074.55 4612.32,6074.39 4611.65,6074.02 4611.13,6073.41 4610.79,6072.47 4603.15,6083.55 4604.53,6083.42 4605.81,6083.44 4608.17,6083.76 4610.54,6084.19
  region net PA5: 4569.35,6336.46 4562.28,6343.53 4563.41,6344.8 4564.43,6346.25 4565.17,6347.82 4565.51,6349.45 4575.26,6339.7 4573.64,6339.36 4572.07,6338.61 4570.62,6337.6
  region net PA5: 4420,5982.05 4430,5982.05 4430.09,5980.35 4430.4,5978.61 4430.99,5976.97 4431.89,5975.58 4418.11,5975.58 4419.01,5976.97 4419.6,5978.61 4419.91,5980.35
  region net VRTC: 3511.87,5888.84 3511.87,5882.84 3510.84,5882.75 3509.93,5882.51 3508.35,5881.62 3506.91,5880.38 3505.39,5878.95 3505.39,5892.73 3506.91,5891.3 3508.35,5890.06 3509.93,5889.17 3510.84,5888.93
  region net VRTC: 3486.58,5882.84 3486.58,5888.84 3487.61,5888.93 3488.52,5889.17 3490.1,5890.06 3491.54,5891.3 3493.06,5892.73 3493.06,5878.95 3491.54,5880.38 3490.1,5881.62 3488.52,5882.51 3487.61,5882.75
  region net BL: 4531.42,7076.05 4521.42,7076.05 4521.33,7077.75 4521.02,7079.5 4520.44,7081.14 4519.53,7082.53 4533.32,7082.53 4532.41,7081.14 4531.83,7079.5 4531.51,7077.75
  region net CS: 3570.4,7587.33 3577.47,7580.26 3576.34,7579 3575.32,7577.54 3574.58,7575.97 3574.24,7574.35 3564.49,7584.1 3566.11,7584.44 3567.68,7585.18 3569.13,7586.2
  region net CLK: 3577.64,7555.36 3577.64,7545.36 3575.94,7545.27 3574.2,7544.96 3572.56,7544.37 3571.17,7543.47 3571.17,7557.25 3572.56,7556.35 3574.2,7555.76 3575.94,7555.45
  region net MISO: 3577.64,7530.86 3577.64,7520.86 3575.94,7520.77 3574.2,7520.46 3572.56,7519.87 3571.17,7518.97 3571.17,7532.75 3572.56,7531.85 3574.2,7531.26 3575.94,7530.95
  region net GBUF: 3479.6,5326.93 3472.53,5334.01 3473.66,5335.27 3474.68,5336.73 3475.42,5338.3 3475.76,5339.92 3485.51,5330.17 3483.89,5329.83 3482.32,5329.09 3480.87,5328.07
  region net PB9: 4420,6266.77 4410,6266.77 4409.91,6268.47 4409.6,6270.21 4409.01,6271.85 4408.11,6273.24 4421.89,6273.24 4420.99,6271.85 4420.4,6270.21 4420.09,6268.47
  region net MP3_RIGHT: 4022.53,5604.56 4029.6,5611.63 4030.87,5610.5 4032.32,5609.48 4033.89,5608.74 4035.51,5608.4 4025.76,5598.64 4025.42,5600.27 4024.68,5601.84 4023.66,5603.29
  region net MP3_LEFT: 4204.18,5634.66 4204.18,5644.66 4205.88,5644.75 4207.62,5645.06 4209.26,5645.65 4210.65,5646.55 4210.65,5632.76 4209.26,5633.67 4207.62,5634.26 4205.88,5634.57
  region net MICN: 4350.3,5816.81 4350.3,5806.81 4348.6,5806.72 4346.86,5806.41 4345.22,5805.83 4343.83,5804.92 4343.83,5818.71 4345.22,5817.8 4346.86,5817.22 4348.6,5816.9
  region net ALDO3: 3372.18,6290.55 3365.11,6297.62 3366.25,6298.89 3367.26,6300.34 3368.01,6301.91 3368.35,6303.54 3378.1,6293.79 3376.47,6293.45 3374.9,6292.7 3373.45,6291.69
  region net ALDO3: 4546.63,5671.42 4546.63,5661.42 4544.93,5661.33 4543.19,5661.02 4541.55,5660.43 4540.16,5659.52 4540.16,5673.31 4541.55,5672.4 4543.19,5671.82 4544.93,5671.51
  region net PE12: 3843.97,5487.3 3843.37,5497.3 3844.99,5497.42 3846.67,5497.8 3848.23,5498.44 3849.5,5499.39 3850.44,5485.63 3849.02,5486.45 3847.38,5486.96 3845.66,5487.23
  region net PE12: 3867.53,5497.3 3867.53,5487.3 3866.08,5487.19 3864.53,5486.88 3863.04,5486.36 3861.8,5485.63 3862.75,5499.39 3863.72,5498.62 3864.97,5497.95 3866.31,5497.48
  region net DCDC1: 4621.9,6643.75 4628.97,6650.82 4630.04,6649.95 4631.38,6649.17 4632.81,6648.59 4634.15,6648.32 4624.4,6638.57 4624.14,6639.91 4623.55,6641.34 4622.77,6642.68
  region net DCDC1: 4570.22,7086.46 4560.22,7086.46 4560.13,7088.16 4559.82,7089.9 4559.24,7091.54 4558.33,7092.93 4572.12,7092.93 4571.21,7091.54 4570.63,7089.9 4570.31,7088.16
  region net FLASH_MOSI: 3912.36,7359.41 3912.36,7369.41 3914.06,7369.5 3915.8,7369.81 3917.44,7370.4 3918.83,7371.3 3918.83,7357.51 3917.44,7358.42 3915.8,7359.01 3914.06,7359.32
  region net FLASH_MISO: 3912.53,7699.81 3919.6,7706.88 3920.87,7705.75 3922.32,7704.73 3923.89,7703.99 3925.51,7703.65 3915.76,7693.89 3915.42,7695.52 3914.68,7697.09 3913.66,7698.54
  region net FLASH_CS: 3949.22,7669.41 3949.22,7679.41 3950.92,7679.5 3952.67,7679.81 3954.31,7680.4 3955.7,7681.3 3955.7,7667.51 3954.31,7668.42 3952.67,7669.01 3950.92,7669.32
  region net DCDC1: 4033.08,7549.01 4026.01,7541.93 4024.74,7543.07 4023.29,7544.09 4021.72,7544.83 4020.09,7545.17 4029.84,7554.92 4030.18,7553.3 4030.93,7551.73 4031.94,7550.27
  region net DCDC1: 4224.56,7351.33 4224.56,7341.33 4222.86,7341.24 4221.12,7340.93 4219.48,7340.34 4218.09,7339.43 4218.09,7353.22 4219.48,7352.31 4221.12,7351.73 4222.86,7351.42
  region net DCDC1: 4647.53,6892.99 4654.6,6900.06 4655.87,6898.92 4657.32,6897.91 4658.89,6897.16 4660.51,6896.82 4650.76,6887.07 4650.42,6888.7 4649.68,6890.27 4648.66,6891.72
  region net DCDC1: 3652.36,7639.41 3652.36,7649.41 3654.06,7649.5 3655.8,7649.81 3657.44,7650.4 3658.83,7651.3 3658.83,7637.51 3657.44,7638.42 3655.8,7639.01 3654.06,7639.32
  region net DCDC1: 3485,7711.77 3475,7711.77 3474.91,7713.47 3474.6,7715.21 3474.01,7716.85 3473.11,7718.24 3486.89,7718.24 3485.99,7716.85 3485.4,7715.21 3485.09,7713.47
  region net DCDC1: 3727.47,7129.01 3720.4,7121.93 3719.13,7123.07 3717.68,7124.09 3716.11,7124.83 3714.49,7125.17 3724.24,7134.92 3724.58,7133.3 3725.32,7131.73 3726.34,7130.27
  region net DCDC1: 4089.05,7081.77 4079.05,7081.77 4078.96,7083.47 4078.65,7085.21 4078.07,7086.85 4077.16,7088.24 4090.95,7088.24 4090.04,7086.85 4089.46,7085.21 4089.15,7083.47
  region net LED_K: 4049.68,7016.41 ccw(c4114.86,7016.41) 4057,6986.41 4045.39,6981.41 4029.68,6986.41 ccw(c3989.68,7016.41) 4039.68,7016.41
  region net MOSI: 4260,7474.41 cw(c4250.62,7474.41) 4252.72,7465.27 4267.44,7455.9 4298.14,7456.38 4300,7466.38 cw(c4300,7526.43) 4270,7474.41
  region net PE11: 3852.09,5577.93 3847.34,5568.54 3845.82,5570.25 3844.45,5571.71 3843.76,5572.17 3843.03,5572.38 3842.25,5572.26 3841.38,5571.75 3842.33,5585.33 3843.78,5583.91 3845.02,5582.9 3847.16,5581.58 3849.33,5580.29 3850.6,5579.31
  region net PE11: 3823.47,5568.88 3818.38,5577.93 3820.02,5579.46 3821.41,5580.54 3823.8,5581.96 3826.23,5583.34 3827.67,5584.37 3829.39,5585.82 3829.43,5572.09 3828.58,5572.65 3827.81,5572.8 3827.1,5572.6 3826.41,5572.13 3825.02,5570.63
  region net BL: 4544.9,6981.28 4544.9,6991.28 ccw(c4544.9,7079.9) 4559.9,6992.56 4559.9,6978.06 ccw(c4544.9,6944.75)
Inner1:
  region net PB9: 3640,6872.05 3650,6872.05 3650.09,6870.35 3650.4,6868.61 3650.99,6866.97 3651.89,6865.58 3638.11,6865.58 3639.01,6866.97 3639.6,6868.61 3639.91,6870.35
  region net PB15: 3615,6907.05 3625,6907.05 3625.09,6905.35 3625.4,6903.61 3625.99,6901.97 3626.89,6900.58 3613.11,6900.58 3614.01,6901.97 3614.6,6903.61 3614.91,6905.35
  region net PB15: 3697.36,7169.41 3697.36,7179.41 3699.06,7179.5 3700.8,7179.81 3702.44,7180.4 3703.83,7181.3 3703.83,7167.51 3702.44,7168.42 3700.8,7169.01 3699.06,7169.32
  region net PB9: 3697.61,7084.41 3697.61,7094.41 3699.31,7094.5 3701.05,7094.81 3702.69,7095.4 3704.08,7096.3 3704.08,7082.51 3702.69,7083.42 3701.05,7084.01 3699.31,7084.32
Inner2:
  region net PE12: 3651.32,7234.97 3641.32,7236.66 3641.26,7238.34 3641.05,7240.04 3640.6,7241.67 3639.85,7243.13 3653.54,7241.45 3652.47,7240.12 3651.79,7238.5 3651.42,7236.73
  region net PE11: 3686.98,7232.67 3676.98,7235.49 3676.85,7238.84 3676.52,7240.44 3675.86,7241.96 3689.36,7239.14 3688.71,7238.56 3688.19,7237.87 3687.46,7236.26 3687.09,7234.48
  region net PE12: 3860.41,5479.78 3850.41,5480.84 3850.34,5482.53 3850.09,5484.25 3849.58,5485.88 3848.77,5487.32 3862.52,5486.25 3861.51,5484.9 3860.86,5483.27 3860.51,5481.51
Bottom Layer:
  drawing of 308 lines, arcs and shapes, not listed

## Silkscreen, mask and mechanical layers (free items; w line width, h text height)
Bottom Silkscreen Layer:
  lines w10: 3395,5389.41 3395,6784.41 ; 3420,5404.41 3420,6279.14 ; 3197.09,5362.2 3197.09,7724.41 4890,7724.41 4890,5362.2 3197.09,5362.2
  text "Arasaka Industry" at 3570,6504.41 h120 r90
  text "[荒坂産業]" at 3705,6089.41 h120 r90
Top Solder Mask Layer:
  text "[Topaz] /  ver1.2" at 3220,6389.41 h120
  text "@EK_Industry" at 4105,5319.41 h120
Mechanical Layer:
  lines w1: 3570.95,6488.08 3570.95,6586.51 4476.46,6586.51 4476.46,6488.08 3570.95,6488.08 ; 4064.11,5482.95 4064.11,5581.38 4536.56,5581.38 4536.56,5482.95 4064.11,5482.95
